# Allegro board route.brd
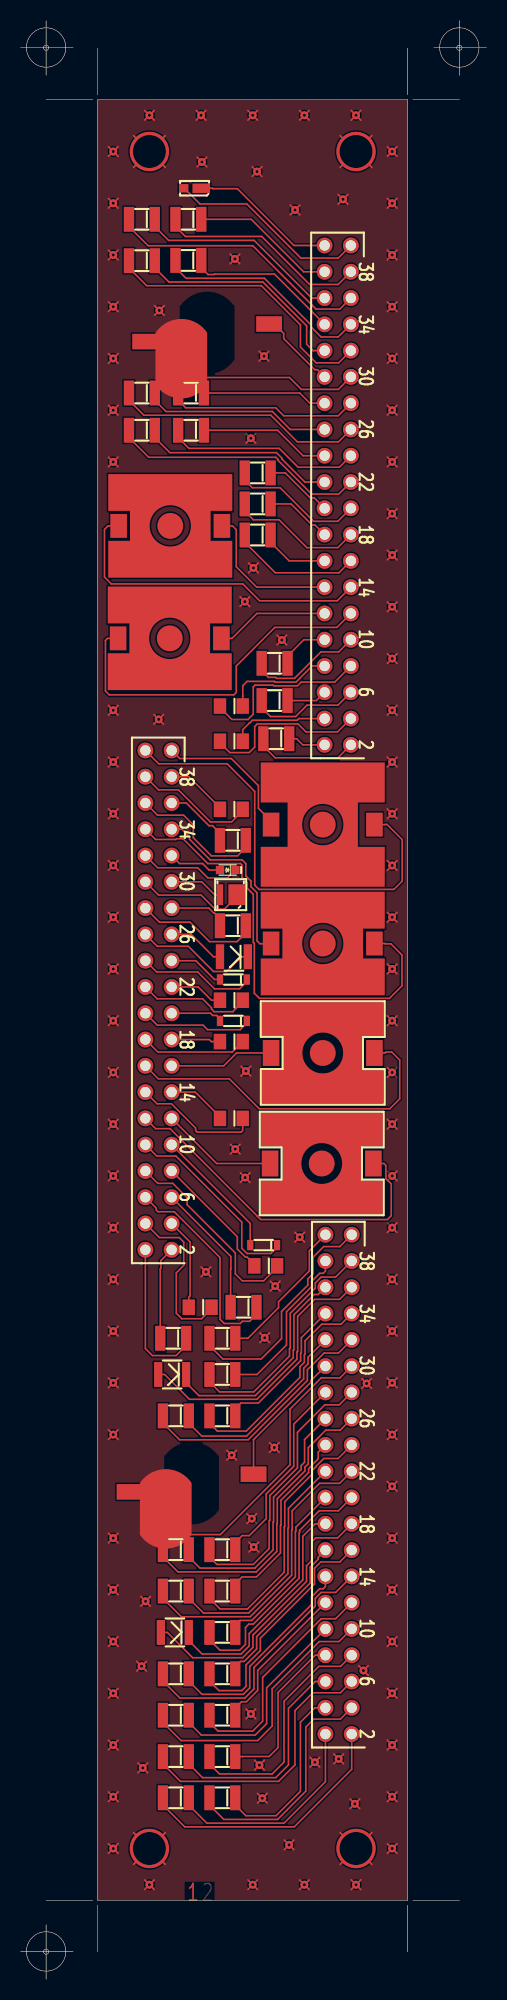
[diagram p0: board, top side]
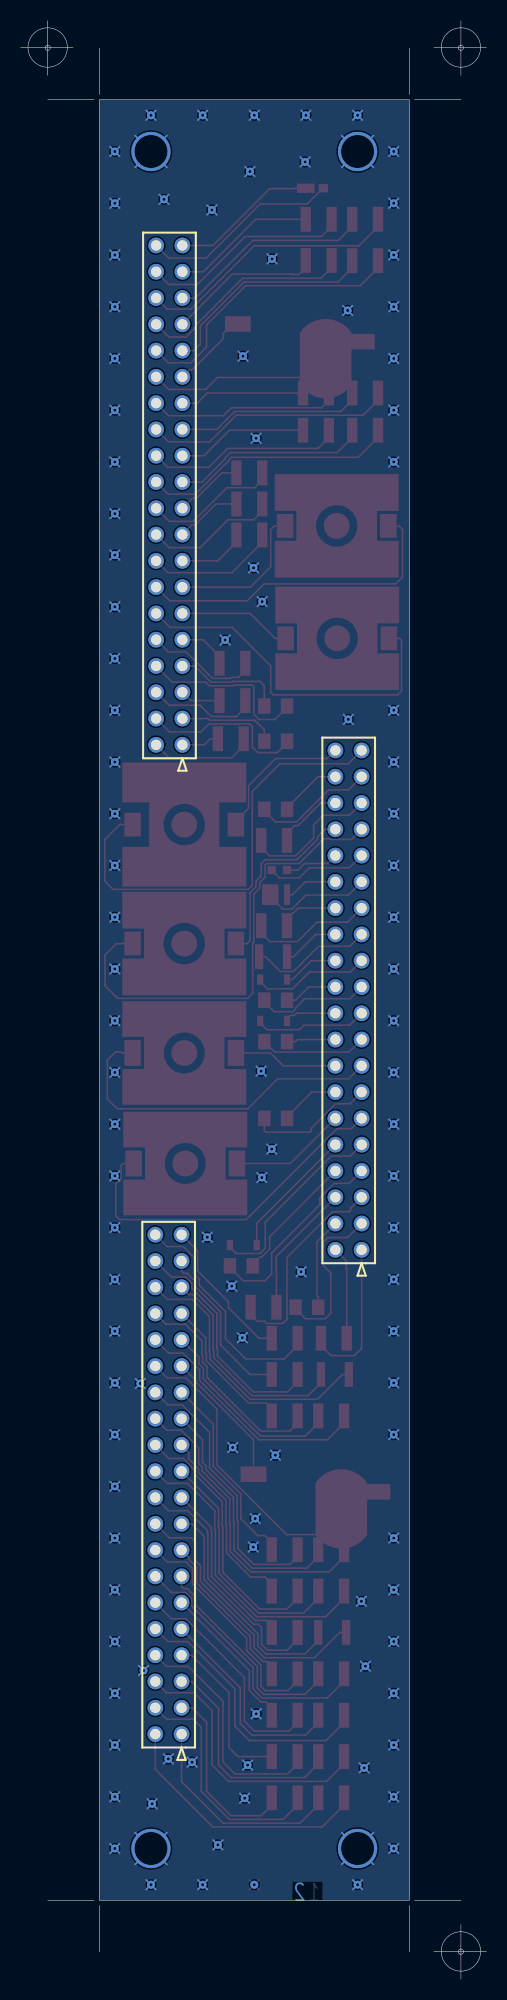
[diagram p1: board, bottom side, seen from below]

Outline 45.08 x 189.28 mm; copper layers: TOP, BOTTOM. Coordinates in mm from the lower left corner of the outline.
Outline path: circle c2.46,186.69 r1.9 ; circle c2.46,186.67 r0.25 ; circle c42.46,186.69 r1.91 ; circle c42.46,186.67 r0.25 ; 0,186.67 5.08,186.67 ; 2.46,189.28 2.46,184 ; 6.96,181.64 2.46,181.64 ; 6.96,7.64 2.46,7.64 ; 7.46,182.14 7.46,186.64 ; 7.46,7.14 7.46,2.64 ; 37.46,182.14 37.46,186.64 ; 37.46,7.14 37.46,2.64 ; 37.96,181.64 42.46,181.64 ; 37.96,7.64 42.46,7.64 ; 40,186.67 45.08,186.67 ; 42.46,189.28 42.46,184 ; 7.46,181.64 37.46,181.64 37.46,7.64 7.46,7.64 7.46,181.64

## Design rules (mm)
constraint set DEFAULT: min track width 0.15, pair gap 0.15

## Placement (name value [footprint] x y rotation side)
D1  -  [LED_JCLMS]  15.88 173.09 270 top
D2  -  [LED_SMC]  14.98 170.09 0 top
D3  -  [LED_SMC]  10.48 170.09 0 top
D4  -  [LED_SMC]  14.98 166.11 0 top
D5  -  [LED_SMC]  10.48 166.09 0 top
D6  -  [LED_APG2C1]  12.05 158.27 270 top
D7  -  [LED_SMC]  15.24 153.3 0 top
D8  -  [LED_SMC]  10.48 153.3 0 top
D9  -  [LED_SMC]  15.24 149.7 0 top
D10  -  [LED_SMC]  10.48 149.7 0 top
D11  -  [LED_SMC]  21.69 145.58 0 top
D12  -  [LED_SMC]  21.69 142.58 0 top
D13  -  [LED_SMC]  21.69 139.58 0 top
D14  -  [LED_LB_W5SM]  9.48 140.46 0 top
D15  -  [LED_LB_W5SM]  9.43 129.59 0 top
D16  -  [LED_SMC]  23.33 127.18 0 top
D17  -  [SLED23X15_0805]  19.29 123.05 0 top
D18  -  [LED_SMC]  23.33 123.58 0 top
D19  -  [SLED23X15_0805]  19.29 119.65 0 top
D20  -  [LED_SMC]  23.49 119.89 0 top
D21  -  [LED_LV_W5AM]  24.24 111.59 0 top
D22  -  [SLED23X15_0805]  19.29 113.07 0 top
D23  -  [LED_SMC]  19.29 110.07 0 top
D24  -  [LED_LB_W5SM]  24.24 100.1 0 top
D25  -  [SLED16X8_0603]  19.29 107.2 0 top
D26  -  [SLED_PSLM31]  19.29 104.82 0 top
D27  -  [LED_SMC]  19.29 101.82 0 top
D28  -  [LED_SMT]  19.29 98.82 0 top
D29  -  [SLED32X10_1204]  19.29 96.62 90 top
D30  -  [SLED23X15_0805]  19.29 94.62 0 top
D31  -  [SLED32X10_1204]  19.29 92.62 90 top
D32  -  [SLED23X15_0805]  19.29 90.62 0 top
D33  -  [LED_LR_W5SM]  24.24 89.52 0 top
D34  -  [SLED23X15_0805]  19.29 83.2 0 top
D35  -  [LED_LR_W5SM]  24.14 78.84 0 top
D36  -  [SLED32X10_1204]  22.22 70.95 90 top
D37  -  [SLED23X15_0805]  22.62 68.95 0 top
D38  -  [LED_SMC]  20.32 64.95 0 top
D39  -  [SLED23X15_0805]  16.27 64.95 0 top
D40  -  [LED_SMC]  13.51 61.95 0 top
D41  -  [LED_SMC]  18.27 61.95 0 top
D42  -  [LED_SMC]  18.27 58.45 0 top
D43  -  [LED_SMT]  13.31 58.45 0 top
D44  -  [LED_SMC]  18.27 54.45 0 top
D45  -  [LED_SMC]  13.77 54.45 0 top
D46  -  [LED_APG2C1]  10.54 47.11 270 top
D47  -  [LED_SMC]  18.27 41.52 0 top
D48  -  [LED_SMC]  13.77 41.52 0 top
D49  -  [LED_SMC]  18.27 37.52 0 top
D50  -  [LED_SMC]  13.77 37.52 0 top
D51  -  [LED_SMC]  18.27 33.52 0 top
D52  -  [LED_SMT]  13.57 33.52 0 top
D53  -  [LED_SMC]  18.27 29.52 0 top
D54  -  [LED_SMC]  13.77 29.52 0 top
D55  -  [LED_SMC]  18.27 25.52 0 top
D56  -  [LED_SMC]  13.77 25.52 0 top
D57  -  [LED_SMC]  18.27 21.52 0 top
D58  -  [LED_SMC]  13.77 21.52 0 top
D59  -  [LED_SMC]  18.27 17.54 0 top
D60  -  [LED_SMC]  13.77 17.54 0 top
J1  -  [CONHE13D2X20M]  29.42 119.3 180 bottom
J2  -  [CONHE13D2X20M]  12.07 70.5 180 bottom
J3  -  [CONHE13D2X20M]  29.5 23.7 180 bottom
NOREF  -  []  2.46 2.64 0 top
NOREF#2  -  []  7.46 7.64 90 top
NOREF#3  -  []  7.46 7.64 0 top

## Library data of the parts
D1 = LED: part number: GW-JCLMS1
D2 = LED: part number: RLCU-355
D3 = LED: part number: RLCU-365
D4 = LED: part number: UVLED365_SMD
D5 = LED: part number: RLCU-375
D6 = LED: part number: APG2C1_375
D7 = LED: part number: RLCU-380
D8 = LED: part number: SMC395
D9 = LED: part number: RLCU-400
D10 = LED: part number: SMC405
D11 = LED: part number: RLCU-410
D12 = LED: part number: SMC415
D13 = LED: part number: SMC430
D14 = LED: part number: LD_W5AM_1U4U_35
D15 = LED: part number: LB_W5SM_FZH_35
D16 = LED: part number: SMC470
D17 = LED: part number: 598-8191-107F
D18 = LED: part number: SMC490
D19 D22 = LED: part number: 598-8181-107F
D20 = LED: part number: RLCU
D21 = LED: part number: LV_W5AM_JZKZ_25
D23 = LED: part number: SMC525
D24 = LED: part number: LT_W5SM-JYKI-25
D25 = LED: part number: LTQ39G
D26 = LED: part number: PSLM31.13
D27 = LED: part number: SMC565
D28 = LED: part number: SMT570
D29 = LED: part number: SM1204SGC
D30 = LED: part number: 598-8150-107F
D31 = LED: part number: SM1204UYC
D32 = LED: part number: 598-8140-107F
D33 = LED: part number: LY_W5SM_HZJZ_46
D34 = LED: part number: 598-8130-107F
D35 = LED: part number: LA_W5SM_JYKY_24
D36 = LED: part number: SM1204UOC
D37 = LED: part number: 598-8120-107F
D38 = LED: part number: SMC630
D39 = LED: part number: 598-8110-107F
D40 D59 D60 = LED: part number: SMCXXX
D41 = LED: part number: SMC660N
D42 = LED: part number: SMC680
D43 = LED: part number: SMT700
D44 = LED: part number: SMC720
D45 = LED: part number: SMC735
D46 = LED: part number: APG2C1_740
D47 = LED: part number: SMC750
D48 = LED: part number: SMC770
D49 = LED: part number: SMC780
D50 = LED: part number: SMC810
D51 = LED: part number: SMC830
D52 = LED: part number: SMT850N
D53 = LED: part number: SMC870
D54 = LED: part number: SMC890
D55 = LED: part number: SMC910
D56 = LED: part number: SMC940
D57 = LED: part number: SMC970
D58 = LED: part number: SMC1050
J1-J3 = CON40P: part number: CON40P-HE13D

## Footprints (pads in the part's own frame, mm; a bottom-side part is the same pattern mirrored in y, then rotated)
CONHE13D2X20M
  round 1.52 hole 1: 1(0,0) 2(-2.54,0) 3(0,2.54) 4(-2.54,2.54) 5(0,5.08) 6(-2.54,5.08) 7(0,7.62) 8(-2.54,7.62) 9(0,10.16) 10(-2.54,10.16) 11(0,12.7) 12(-2.54,12.7) 13(0,15.24) 14(-2.54,15.24) 15(0,17.78) 16(-2.54,17.78) 17(0,20.32) 18(-2.54,20.32) 19(0,22.86) 20(-2.54,22.86) 21(0,25.4) 22(-2.54,25.4) 23(0,27.94) 24(-2.54,27.94) 25(0,30.48) 26(-2.54,30.48) 27(0,33.02) 28(-2.54,33.02) 29(0,35.56) 30(-2.54,35.56) 31(0,38.1) 32(-2.54,38.1) 33(0,40.64) 34(-2.54,40.64) 35(0,43.18) 36(-2.54,43.18) 37(0,45.72) 38(-2.54,45.72) 39(0,48.26) 40(-2.54,48.26)
LED_APG2C1
  custom 1.25x1.25 smd: (1.65,3.5)
  rect 1.5x2.5 smd: 1(0,0) 2(-1.7,12)
LED_JCLMS
  rect 0.8x0.9 smd: 1(0,-0.1)
  rect 0.9x1.7 smd: 2(0,1.6)
LED_LB_W5SM
  round 2.5 smd: (5,0)
  rect 1.6x2.3 smd: 1(0,0) 2(10,0)
LED_LR_W5SM
  round 2.5 smd: (5,0)
  rect 1.6x2.5 smd: 1(0,0) 2(10,0)
LED_LV_W5AM
  round 2.5 smd: (5,0)
  rect 1.6x2.3 smd: 1(0,0) 2(10,0)
LED_SMC
  rect 1x2.4 smd: 1(0,0) 2(2.5,0)
LED_SMT
  rect 0.8x2.4 smd: 1(0,0) 2(2.7,0)
SLED16X8_0603
  rect 0.8x0.8 smd: 1(0,0) 2(1.5,0)
SLED23X15_0805
  rect 1.2x1.5 smd: 1(0,0) 2(2.2,0)
SLED32X10_1204
  rect 1x0.6 smd: 1(0,0) 2(0,-2.6)
SLED_PSLM31
  rect 0.6x2 smd: 1(0,0)
  rect 1.6x2 smd: 2(1.62,0)

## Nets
UNNAMED_1_CON40P_I2_A: D4.2(K) J1.33
UNNAMED_1_CON40P_I2_A_1: D20.2(K) J1.1
UNNAMED_1_CON40P_I2_A_2: D18.1 J1.6
UNNAMED_1_CON40P_I2_A_3: D5.1 J1.32
UNNAMED_1_CON40P_I2_A_4: D5.2(K) J1.31
UNNAMED_1_CON40P_I2_A_5: D6.1 J1.30
UNNAMED_1_CON40P_I2_A_6: D6.2(K) J1.29
UNNAMED_1_CON40P_I2_A_7: D4.1 J1.34
UNNAMED_1_CON40P_I2_A_8: D10.1 J1.22
UNNAMED_1_CON40P_I2_A_9: D10.2(K) J1.21
UNNAMED_1_CON40P_I2_A_10: D8.1 J1.26
UNNAMED_1_CON40P_I2_A_11: D15.2(K) J1.11
UNNAMED_1_CON40P_I2_A_12: D15.1 J1.12
UNNAMED_1_CON40P_I2_A_13: D8.2(K) J1.25
UNNAMED_1_CON40P_I2_A_14: D7.1 J1.28
UNNAMED_1_CON40P_I2_A_15: D7.2(K) J1.27
UNNAMED_1_CON40P_I2_A_16: D14.1 J1.14
UNNAMED_1_CON40P_I2_A_17: D14.2(K) J1.13
UNNAMED_1_CON40P_I2_A_18: D13.1 J1.16
UNNAMED_1_CON40P_I2_A_19: D13.2(K) J1.15
UNNAMED_1_CON40P_I2_A_20: D12.1 J1.18
UNNAMED_1_CON40P_I2_A_21: D12.2(K) J1.17
UNNAMED_1_CON40P_I2_A_22: D9.2(K) J1.23
UNNAMED_1_CON40P_I2_A_23: D9.1 J1.24
UNNAMED_1_CON40P_I2_A_24: D11.2(K) J1.19
UNNAMED_1_CON40P_I2_A_25: D11.1 J1.20
UNNAMED_1_CON40P_I2_A_26: D16.2(K) J1.9
UNNAMED_1_CON40P_I2_A_27: D16.1 J1.10(A<9>)
UNNAMED_1_CON40P_I2_A_28: D17.1 J1.8
UNNAMED_1_CON40P_I2_A_29: D17.2(K) J1.7
UNNAMED_1_CON40P_I2_A_30: D18.2(K) J1.5
UNNAMED_1_CON40P_I2_A_31: D20.1 J1.2
UNNAMED_1_CON40P_I2_A_32: D19.2(K) J1.3
UNNAMED_1_CON40P_I2_A_33: D19.1 J1.4
UNNAMED_1_CON40P_I2_A_34: D3.1 J1.36
UNNAMED_1_CON40P_I2_A_35: D2.1 J1.38
UNNAMED_1_CON40P_I2_A_36: D2.2(K) J1.37
UNNAMED_1_CON40P_I2_A_37: D3.2(K) J1.35
UNNAMED_1_CON40P_I2_A_38: D1.2(K) J1.39
UNNAMED_1_CON40P_I2_A_39: D1.1 J1.40
UNNAMED_1_CON40P_I21_A: D35.2(K) J2.11
UNNAMED_1_CON40P_I21_A_1: D23.2(K) J2.35
UNNAMED_1_CON40P_I21_A_2: D23.1 J2.36
UNNAMED_1_CON40P_I21_A_3: D35.1 J2.12
UNNAMED_1_CON40P_I21_A_4: D27.2(K) J2.27
UNNAMED_1_CON40P_I21_A_5: D27.1 J2.28
UNNAMED_1_CON40P_I21_A_6: D33.2(K) J2.15
UNNAMED_1_CON40P_I21_A_7: D33.1 J2.16
UNNAMED_1_CON40P_I21_A_8: D24.2(K) J2.33
UNNAMED_1_CON40P_I21_A_9: D24.1 J2.34
UNNAMED_1_CON40P_I21_A_10: D30.1 J2.22
UNNAMED_1_CON40P_I21_A_11: D21.2(K) J2.39
UNNAMED_1_CON40P_I21_A_12: D30.2(K) J2.21
UNNAMED_1_CON40P_I21_A_13: D21.1 J2.40
UNNAMED_1_CON40P_I21_A_14: D32.1 J2.18
UNNAMED_1_CON40P_I21_A_15: D32.2(K) J2.17
UNNAMED_1_CON40P_I21_A_16: D40.2(K) J2.1
UNNAMED_1_CON40P_I21_A_17: D40.1 J2.2
UNNAMED_1_CON40P_I21_A_18: D22.2(K) J2.37
UNNAMED_1_CON40P_I21_A_19: D22.1 J2.38
UNNAMED_1_CON40P_I21_A_20: D39.2(K) J2.3
UNNAMED_1_CON40P_I21_A_21: D37.1 J2.8
UNNAMED_1_CON40P_I21_A_22: D39.1 J2.4
UNNAMED_1_CON40P_I21_A_23: D37.2(K) J2.7
UNNAMED_1_CON40P_I21_A_24: D25.2(K) J2.31
UNNAMED_1_CON40P_I21_A_25: D25.1 J2.32
UNNAMED_1_CON40P_I21_A_26: D38.1 J2.6
UNNAMED_1_CON40P_I21_A_27: D28.2(K) J2.25
UNNAMED_1_CON40P_I21_A_28: D38.2(K) J2.5
UNNAMED_1_CON40P_I21_A_29: D28.1 J2.26
UNNAMED_1_CON40P_I21_A_30: D36.1 J2.10(A<9>)
UNNAMED_1_CON40P_I21_A_31: D31.1 J2.20
UNNAMED_1_CON40P_I21_A_32: D34.1 J2.14
UNNAMED_1_CON40P_I21_A_33: D34.2(K) J2.13
UNNAMED_1_CON40P_I21_A_34: D29.1 J2.24
UNNAMED_1_CON40P_I21_A_35: D36.2(K) J2.9
UNNAMED_1_CON40P_I21_A_36: D31.2(K) J2.19
UNNAMED_1_CON40P_I21_A_37: D29.2(K) J2.23
UNNAMED_1_CON40P_I21_A_38: D26.1 J2.30
UNNAMED_1_CON40P_I21_A_39: D26.2(K) J2.29
UNNAMED_1_CON40P_I55_A: D46.2(K) J3.29
UNNAMED_1_CON40P_I55_A_1: D46.1 J3.30
UNNAMED_1_CON40P_I55_A_2: D41.1 J3.40
UNNAMED_1_CON40P_I55_A_3: D41.2(K) J3.39
UNNAMED_1_CON40P_I55_A_4: D58.1 J3.6
UNNAMED_1_CON40P_I55_A_5: D58.2(K) J3.5
UNNAMED_1_CON40P_I55_A_6: D55.1 J3.12
UNNAMED_1_CON40P_I55_A_7: D55.2(K) J3.11
UNNAMED_1_CON40P_I55_A_8: D56.1 J3.10(A<9>)
UNNAMED_1_CON40P_I55_A_9: D57.1 J3.8
UNNAMED_1_CON40P_I55_A_10: D56.2(K) J3.9
UNNAMED_1_CON40P_I55_A_11: D57.2(K) J3.7
UNNAMED_1_CON40P_I55_A_12: D54.1 J3.14
UNNAMED_1_CON40P_I55_A_13: D54.2(K) J3.13
UNNAMED_1_CON40P_I55_A_14: D53.1 J3.16
UNNAMED_1_CON40P_I55_A_15: D53.2(K) J3.15
UNNAMED_1_CON40P_I55_A_16: D59.2(K) J3.3
UNNAMED_1_CON40P_I55_A_17: D59.1 J3.4
UNNAMED_1_CON40P_I55_A_18: D51.1 J3.20
UNNAMED_1_CON40P_I55_A_19: D51.2(K) J3.19
UNNAMED_1_CON40P_I55_A_20: D48.1 J3.26
UNNAMED_1_CON40P_I55_A_21: D48.2(K) J3.25
UNNAMED_1_CON40P_I55_A_22: D49.1 J3.24
UNNAMED_1_CON40P_I55_A_23: D49.2(K) J3.23
UNNAMED_1_CON40P_I55_A_24: D50.1 J3.22
UNNAMED_1_CON40P_I55_A_25: D50.2(K) J3.21
UNNAMED_1_CON40P_I55_A_26: D47.1 J3.28
UNNAMED_1_CON40P_I55_A_27: D47.2(K) J3.27
UNNAMED_1_CON40P_I55_A_28: D60.2(K) J3.1
UNNAMED_1_CON40P_I55_A_29: D60.1 J3.2
UNNAMED_1_CON40P_I55_A_30: D45.1 J3.32
UNNAMED_1_CON40P_I55_A_31: D45.2(K) J3.31
UNNAMED_1_CON40P_I55_A_32: D43.2(K) J3.35
UNNAMED_1_CON40P_I55_A_33: D43.1 J3.36
UNNAMED_1_CON40P_I55_A_34: D44.1 J3.34
UNNAMED_1_CON40P_I55_A_35: D44.2(K) J3.33
UNNAMED_1_CON40P_I55_A_36: D52.2(K) J3.17
UNNAMED_1_CON40P_I55_A_37: D42.1 J3.38
UNNAMED_1_CON40P_I55_A_38: D42.2(K) J3.37
UNNAMED_1_CON40P_I55_A_39: D52.1 J3.18

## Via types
v1: diameter 0.77, hole 0.3, TOP to BOTTOM, 107 vias
v2: diameter 3.8, hole 3.2, TOP to BOTTOM, 4 vias

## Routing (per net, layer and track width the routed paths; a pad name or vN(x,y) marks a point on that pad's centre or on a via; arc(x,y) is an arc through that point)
GND: length 623.5
  TOP w0.15: v1(27.46,180.14) 27.93,179.68 ; v1(27.46,180.14) 27,179.68 ; v1(27.46,180.14) 27.93,180.61 ; v1(27.46,180.14) 27,180.61 ; v1(13.36,121.76) 13.83,122.23 ; v1(13.36,121.76) 12.9,122.23 ; v1(13.36,121.76) 12.9,121.3 ; v1(13.36,121.76) 13.83,121.3 ; v1(23.55,156.86) 24.02,156.4 ; v1(23.55,156.86) 23.09,156.4 ; v1(23.55,156.86) 23.09,157.33 ; v1(23.55,156.86) 24.02,157.33 ; v1(22.37,44.52) 22.84,44.99 ; v1(22.37,44.52) 21.91,44.99 ; v1(22.37,44.52) 21.91,44.06 ; v1(35.96,82.64) 36.43,82.18 ; v1(35.96,82.64) 36.43,83.11 ; v1(35.96,82.64) 35.5,82.18 ; v1(35.96,82.64) 35.5,83.11 ; 35.5,23.11 v1(35.96,22.64) ; v1(35.96,22.64) 35.5,22.18 ; v1(35.96,22.64) 36.43,23.11 ; v1(35.96,22.64) 36.43,22.18 ; 8.5,33.11 v1(8.96,32.64) ; v1(8.96,32.64) 9.43,32.18 ; v1(8.96,32.64) 9.43,33.11 ; v1(8.96,32.64) 8.5,32.18 ; 35.5,47.18 v1(35.96,47.64) ; v1(35.96,47.64) 36.43,48.11 ; v1(35.96,47.64) 36.43,47.18 ; v1(35.96,47.64) 35.5,48.11 ; v1(21.8,87.77) 22.27,88.24 ; v1(21.8,87.77) 21.34,88.24 ; v1(21.8,87.77) 21.34,87.31 ; v1(21.8,87.77) 22.27,87.31 ; 22.93,17.04 v1(23.39,17.5) ; v1(23.39,17.5) 22.93,17.97 ; v1(23.39,17.5) 23.86,17.04 ; v1(23.39,17.5) 23.86,17.97 ; v1(21.73,77.48) 22.2,77.95 ; v1(21.73,77.48) 22.2,77.02 ; v1(21.73,77.48) 21.27,77.02 ; v1(21.73,77.48) 21.27,77.95 ; 20.31,80.7 v1(20.77,80.23) ; v1(20.77,80.23) 20.31,79.77 ; v1(20.77,80.23) 21.24,79.77 ; v1(20.77,80.23) 21.24,80.7 ; v1(22.46,9.14) 22.93,8.68 ; v1(22.46,9.14) 22.93,9.61 ; v1(22.46,9.14) 22,8.68 ; v1(22.46,9.14) 22,9.61 ; 8.5,27.18 v1(8.96,27.64) ; v1(8.96,27.64) 8.5,28.11 ; v1(8.96,27.64) 9.43,27.18 ; v1(8.96,27.64) 9.43,28.11 ; 35.5,88.11 v1(35.96,87.64) 35.5,87.18 ; 35.5,108.11 v1(35.96,107.64) ; v1(35.96,107.64) 35.5,107.18 ; v1(35.96,107.64) 36.43,107.18 ; v1(35.96,107.64) 36.43,108.11 ; v1(32.35,16.96) 32.82,16.5 ; v1(32.35,16.96) 32.82,17.43 ; v1(32.35,16.96) 31.89,17.43 ; v1(32.35,16.96) 31.89,16.5 ; v1(8.96,22.64) 9.43,22.18 ; v1(8.96,22.64) 8.5,23.11 ; v1(8.96,22.64) 9.43,23.11 ; v1(8.96,22.64) 8.5,22.18 ; 33.03,57.12 v1(33.49,57.58) ; v1(33.49,57.58) 33.96,58.05 ; v1(33.49,57.58) 33.03,58.05 ; v1(33.49,57.58) 33.96,57.12 ; 8.5,122.18 v1(8.96,122.64) ; v1(8.96,122.64) 9.43,123.11 ; v1(8.96,122.64) 9.43,122.18 ; v1(8.96,122.64) 8.5,123.11 ; 8.5,13.11 v1(8.96,12.64) ; v1(8.96,12.64) 9.43,12.18 ; v1(8.96,12.64) 9.43,13.11 ; v1(8.96,12.64) 8.5,12.18 ; v1(8.96,67.64) 9.43,67.18 ; v1(8.96,67.64) 8.5,67.18 ; v1(8.96,67.64) 9.43,68.11 ; v1(8.96,67.64) 8.5,68.11 ; v1(8.96,156.64) 9.43,156.18 ; v1(8.96,156.64) 8.5,156.18 ; v1(8.96,156.64) 8.5,157.11 ; v1(8.96,156.64) 9.43,157.11 ; v1(17.54,175.63) 18.01,175.17 ; v1(17.54,175.63) 18.01,176.1 ; v1(17.54,175.63) 17.08,175.17 ; v1(17.54,175.63) 17.08,176.1 ; 8.5,73.11 v1(8.96,72.64) ; v1(8.96,72.64) 8.5,72.18 ; v1(8.96,72.64) 9.43,72.18 ; v1(8.96,72.64) 9.43,73.11 ; 22,179.68 v1(22.46,180.14) ; v1(22.46,180.14) 22,180.61 ; v1(22.46,180.14) 22.93,179.68 ; v1(22.46,180.14) 22.93,180.61 ; v1(21.7,133.14) 22.17,133.61 ; v1(21.7,133.14) 22.17,132.68 ; v1(21.7,133.14) 21.24,132.68 ; v1(21.7,133.14) 21.24,133.61 ; v1(23.11,20.7) 23.58,21.17 ; v1(23.11,20.7) 22.65,21.17 ; v1(23.11,20.7) 22.65,20.24 ; v1(23.11,20.7) 23.58,20.24 ; v2(32.46,176.64) 34,175.11 ; v2(32.46,176.64) 30.93,178.18 ; v2(32.46,176.64) 30.93,175.11 ; v2(32.46,176.64) 34,178.18 ; 35.5,142.11 v1(35.96,141.64) ; v1(35.96,141.64) 36.43,142.11 ; v1(35.96,141.64) 35.5,141.18 ; v1(35.96,141.64) 36.43,141.18 ; 8.5,88.11 v1(8.96,87.64) ; v1(8.96,87.64) 9.43,88.11 ; v1(8.96,87.64) 9.43,87.18 ; v1(8.96,87.64) 8.5,87.18 ; v1(32.46,9.14) 32.93,8.68 ; v1(32.46,9.14) 32,9.61 ; v1(32.46,9.14) 32,8.68 ; v1(32.46,9.14) 32.93,9.61 ; 8.5,147.11 v1(8.96,146.64) ; v1(8.96,146.64) 8.5,146.18 ; v1(8.96,146.64) 9.43,147.11 ; v1(8.96,146.64) 9.43,146.18 ; v1(35.96,137.64) 36.43,138.11 ; v1(35.96,137.64) 35.5,137.18 ; v1(35.96,137.64) 36.43,137.18 ; v1(35.96,137.64) 35.5,138.11 ; 8.5,58.11 v1(8.96,57.64) ; v1(8.96,57.64) 9.43,58.11 ; v1(8.96,57.64) 8.5,57.18 ; v1(8.96,57.64) 9.43,57.18 ; 35.5,167.11 v1(35.96,166.64) ; v1(35.96,166.64) 36.43,167.11 ; v1(35.96,166.64) 36.43,166.18 ; v1(35.96,166.64) 35.5,166.18 ; 8.5,112.18 v1(8.96,112.64) ; v1(8.96,112.64) 9.43,112.18 ; v1(8.96,112.64) 8.5,113.11 ; v1(8.96,112.64) 9.43,113.11 ; v1(35.96,92.64) 36.43,92.18 ; v1(35.96,92.64) 36.43,93.11 ; v1(35.96,92.64) 35.5,92.18 ; v1(35.96,92.64) 35.5,93.11 ; 11.24,30.73 v1(11.7,30.26) ; v1(11.7,30.26) 12.17,30.73 ; v1(11.7,30.26) 12.17,29.8 ; v1(11.7,30.26) 11.24,29.8 ; 8.5,92.18 v1(8.96,92.64) ; v1(8.96,92.64) 9.43,93.11 ; v1(8.96,92.64) 9.43,92.18 ; v1(8.96,92.64) 8.5,93.11 ; v1(35.96,42.64) 36.43,43.11 ; v1(35.96,42.64) 36.43,42.18 ; v1(35.96,42.64) 35.5,42.18 ; v1(35.96,42.64) 35.5,43.11 ; v1(35.96,122.64) 36.43,123.11 ; v1(35.96,122.64) 35.5,122.18 ; v1(35.96,122.64) 36.43,122.18 ; v1(35.96,122.64) 35.5,123.11 ; 21.82,148.47 v1(22.28,148.93) 22.75,148.47 ; 8.5,177.11 v1(8.96,176.64) ; v1(8.96,176.64) 9.43,177.11 ; v1(8.96,176.64) 9.43,176.18 ; v1(8.96,176.64) 8.5,176.18 ; 35.5,177.11 v1(35.96,176.64) ; v1(35.96,176.64) 36.43,177.11 ; v1(35.96,176.64) 35.5,176.18 ; v1(35.96,176.64) 36.43,176.18 ; 30.93,11.11 v2(32.46,12.64) ; v2(32.46,12.64) 34,14.18 ; v2(32.46,12.64) 30.93,14.18 ; v2(32.46,12.64) 34,11.11 ; 8.5,98.11 v1(8.96,97.64) ; v1(8.96,97.64) 8.5,97.18 ; v1(8.96,97.64) 9.43,97.18 ; v1(8.96,97.64) 9.43,98.11 ; v1(8.96,17.64) 9.43,18.11 ; v1(8.96,17.64) 8.5,18.11 ; v1(8.96,17.64) 9.43,17.18 ; v1(8.96,17.64) 8.5,17.18 ; v1(22.88,174.7) 23.35,174.24 ; v1(22.88,174.7) 23.35,175.17 ; v1(22.88,174.7) 22.42,174.24 ; v1(22.88,174.7) 22.42,175.17 ; 8.5,63.11 v1(8.96,62.64) ; v1(8.96,62.64) 9.43,63.11 ; v1(8.96,62.64) 9.43,62.18 ; v1(8.96,62.64) 8.5,62.18 ; v1(35.96,97.64) 36.43,97.18 ; v1(35.96,97.64) 35.5,98.11 ; v1(35.96,97.64) 35.5,97.18 ; v1(35.96,97.64) 36.43,98.11 ; 35.5,146.18 v1(35.96,146.64) ; v1(35.96,146.64) 36.43,147.11 ; v1(35.96,146.64) 35.5,147.11 ; v1(35.96,146.64) 36.43,146.18 ; 35.5,58.11 v1(35.96,57.64) ; v1(35.96,57.64) 36.43,58.11 ; v1(35.96,57.64) 35.5,57.18 ; v1(35.96,57.64) 36.43,57.18 ; v1(35.96,17.64) 36.43,17.18 ; v1(35.96,17.64) 35.5,18.11 ; v1(35.96,17.64) 36.43,18.11 ; v1(35.96,17.64) 35.5,17.18 ; 24.09,51.86 v1(24.55,51.39) ; v1(24.55,51.39) 25.02,51.86 ; v1(24.55,51.39) 24.09,50.93 ; v1(24.55,51.39) 25.02,50.93 ; v1(17.46,180.14) 17.93,179.68 ; v1(17.46,180.14) 17,179.68 ; v1(17.46,180.14) 17,180.61 ; v1(17.46,180.14) 17.93,180.61 ; 35.5,172.11 v1(35.96,171.64) ; v1(35.96,171.64) 36.43,171.18 ; v1(35.96,171.64) 35.5,171.18 ; v1(35.96,171.64) 36.43,172.11 ; v1(8.96,107.64) 9.43,107.18 ; v1(8.96,107.64) 8.5,108.11 ; v1(8.96,107.64) 8.5,107.18 ; v1(8.96,107.64) 9.43,108.11 ; v1(35.96,72.64) 36.43,72.18 ; v1(35.96,72.64) 36.43,73.11 ; v1(35.96,72.64) 35.5,72.18 ; v1(27.46,9.14) 27.93,9.61 ; v1(27.46,9.14) 27.93,8.68 ; v1(27.46,9.14) 27,9.61 ; v1(27.46,9.14) 27,8.68 ; 23.16,62.47 v1(23.62,62) ; v1(23.62,62) 24.09,62.47 ; v1(23.62,62) 23.16,61.54 ; v1(23.62,62) 24.09,61.54 ; 20.28,166.73 v1(20.74,166.26) ; v1(20.74,166.26) 21.21,166.73 ; v1(20.74,166.26) 21.21,165.8 ; v1(20.74,166.26) 20.28,165.8 ; 8.5,172.11 v1(8.96,171.64) ; v1(8.96,171.64) 9.43,172.11 ; v1(8.96,171.64) 9.43,171.18 ; v1(8.96,171.64) 8.5,171.18 ; v1(27.01,71.72) 27.48,72.19 ; v1(27.01,71.72) 26.55,72.19 ; v1(27.01,71.72) 27.48,71.26 ; v1(27.01,71.72) 26.55,71.26 ; 22.1,42.24 v1(22.56,41.77) ; v1(22.56,41.77) 22.1,41.31 ; v1(22.56,41.77) 23.03,42.24 ; v1(22.56,41.77) 23.03,41.31 ; 11.63,36.07 v1(12.09,36.53) ; v1(12.09,36.53) 12.56,37 ; v1(12.09,36.53) 11.63,37 ; v1(12.09,36.53) 12.56,36.07 ; v1(8.96,52.64) 9.43,53.11 ; v1(8.96,52.64) 8.5,53.11 ; v1(8.96,52.64) 8.5,52.18 ; v1(8.96,52.64) 9.43,52.18 ; v1(8.96,117.64) 9.43,118.11 ; v1(8.96,117.64) 8.5,117.18 ; v1(8.96,117.64) 9.43,117.18 ; v1(8.96,117.64) 8.5,118.11 ; v1(17.93,68.37) 18.4,68.84 ; v1(17.93,68.37) 17.47,68.84 ; v1(17.93,68.37) 17.47,67.91 ; v1(17.93,68.37) 18.4,67.91 ; v1(28.48,20.98) 28.95,21.45 ; v1(28.48,20.98) 28.02,21.45 ; v1(28.48,20.98) 28.02,20.52 ; v1(28.48,20.98) 28.95,20.52 ; 22.07,136.87 v1(22.53,136.4) ; v1(22.53,136.4) 23,135.94 ; v1(22.53,136.4) 23,136.87 ; v1(22.53,136.4) 22.07,135.94 ; 30.32,20.84 v1(30.78,21.3) ; v1(30.78,21.3) 30.32,21.77 ; v1(30.78,21.3) 31.25,21.77 ; v1(30.78,21.3) 31.25,20.84 ; 26.1,171.46 v1(26.56,170.99) ; v1(26.56,170.99) 26.1,170.53 ; v1(26.56,170.99) 27.03,171.46 ; v1(26.56,170.99) 27.03,170.53 ; v1(35.96,52.64) 36.43,53.11 ; v1(35.96,52.64) 35.5,52.18 ; v1(35.96,52.64) 36.43,52.18 ; v1(35.96,52.64) 35.5,53.11 ; v1(12.46,9.14) 12.93,8.68 ; v1(12.46,9.14) 12,9.61 ; v1(12.46,9.14) 12,8.68 ; v1(12.46,9.14) 12.93,9.61 ; 8.5,42.18 v1(8.96,42.64) ; v1(8.96,42.64) 9.43,42.18 ; v1(8.96,42.64) 8.5,43.11 ; v1(8.96,42.64) 9.43,43.11 ; v1(35.96,117.64) 36.43,118.11 ; v1(35.96,117.64) 35.5,117.18 ; v1(35.96,117.64) 36.43,117.18 ; v1(35.96,117.64) 35.5,118.11 ; 35.5,102.18 v1(35.96,102.64) ; v1(35.96,102.64) 36.43,102.18 ; v1(35.96,102.64) 36.43,103.11 ; v1(35.96,102.64) 35.5,103.11 ; 19.96,50.19 v1(20.42,50.65) ; v1(20.42,50.65) 20.89,50.19 ; v1(20.42,50.65) 20.89,51.12 ; v1(20.42,50.65) 19.96,51.12 ; 35.5,67.18 v1(35.96,67.64) ; v1(35.96,67.64) 35.5,68.11 ; v1(35.96,67.64) 36.43,67.18 ; v1(35.96,67.64) 36.43,68.11 ; 10.93,11.11 v2(12.46,12.64) ; v2(12.46,12.64) 14,11.11 ; v2(12.46,12.64) 10.93,14.18 ; v2(12.46,12.64) 14,14.18 ; v1(33.18,29.84) 33.65,30.31 ; v1(33.18,29.84) 32.72,30.31 ; v1(33.18,29.84) 33.65,29.38 ; 12.96,160.82 v1(13.42,161.28) ; v1(13.42,161.28) 13.89,160.82 ; v1(13.42,161.28) 12.96,161.75 ; v1(13.42,161.28) 13.89,161.75 ; v1(8.96,151.64) 9.43,151.18 ; v1(8.96,151.64) 9.43,152.11 ; v1(8.96,151.64) 8.5,151.18 ; v1(8.96,151.64) 8.5,152.11 ; v1(35.96,127.64) 36.43,127.18 ; v1(35.96,127.64) 35.5,128.11 ; v1(35.96,127.64) 35.5,127.18 ; v1(35.96,127.64) 36.43,128.11 ; v1(32.46,180.14) 32.93,180.61 ; v1(32.46,180.14) 32.93,179.68 ; v1(32.46,180.14) 32,180.61 ; v1(32.46,180.14) 32,179.68 ; v1(11.82,20.43) 12.29,20.9 ; v1(11.82,20.43) 11.36,20.9 ; v1(11.82,20.43) 12.29,19.97 ; v1(11.82,20.43) 11.36,19.97 ; v1(8.96,161.64) 9.43,161.18 ; v1(8.96,161.64) 8.5,162.11 ; v1(8.96,161.64) 8.5,161.18 ; v1(8.96,161.64) 9.43,162.11 ; 35.5,38.11 v1(35.96,37.64) ; v1(35.96,37.64) 36.43,38.11 ; v1(35.96,37.64) 36.43,37.18 ; v1(35.96,37.64) 35.5,37.18 ; v2(12.46,176.64) 14,175.11 ; v2(12.46,176.64) 10.93,178.18 ; v2(12.46,176.64) 10.93,175.11 ; v2(12.46,176.64) 14,178.18 ; 35.5,62.18 v1(35.96,62.64) ; v1(35.96,62.64) 36.43,63.11 ; v1(35.96,62.64) 36.43,62.18 ; v1(35.96,62.64) 35.5,63.11 ; 8.5,37.18 v1(8.96,37.64) ; v1(8.96,37.64) 9.43,37.18 ; v1(8.96,37.64) 9.43,38.11 ; v1(8.96,37.64) 8.5,38.11 ; v1(12.46,180.14) 12.93,179.68 ; v1(12.46,180.14) 12.93,180.61 ; v1(12.46,180.14) 12,180.61 ; v1(12.46,180.14) 12,179.68 ; 8.5,167.11 v1(8.96,166.64) ; v1(8.96,166.64) 8.5,166.18 ; v1(8.96,166.64) 9.43,166.18 ; v1(8.96,166.64) 9.43,167.11 ; 8.5,83.11 v1(8.96,82.64) ; v1(8.96,82.64) 8.5,82.18 ; v1(8.96,82.64) 9.43,83.11 ; v1(8.96,82.64) 9.43,82.18 ; 35.5,33.11 v1(35.96,32.64) ; v1(35.96,32.64) 36.43,33.11 ; v1(35.96,32.64) 36.43,32.18 ; v1(35.96,32.64) 35.5,32.18 ; v1(35.96,12.64) 36.43,12.18 ; v1(35.96,12.64) 36.43,13.11 ; v1(35.96,12.64) 35.5,12.18 ; v1(35.96,12.64) 35.5,13.11 ; v1(31.2,172.02) 31.67,172.49 ; v1(31.2,172.02) 31.67,171.56 ; v1(31.2,172.02) 30.74,171.56 ; v1(31.2,172.02) 30.74,172.49 ; 35.5,112.18 v1(35.96,112.64) ; v1(35.96,112.64) 35.5,113.11 ; v1(35.96,112.64) 36.43,112.18 ; v1(35.96,112.64) 36.43,113.11 ; v1(24.64,66.99) 25.11,67.46 ; v1(24.64,66.99) 24.18,67.46 ; v1(24.64,66.99) 24.18,66.53 ; v1(24.64,66.99) 25.11,66.53 ; 25.52,12.53 v1(25.98,12.99) ; v1(25.98,12.99) 25.52,13.46 ; v1(25.98,12.99) 26.45,12.53 ; v1(25.98,12.99) 26.45,13.46 ; 24.82,128.97 v1(25.28,129.43) ; v1(25.28,129.43) 24.82,129.9 ; v1(25.28,129.43) 25.75,128.97 ; v1(25.28,129.43) 25.75,129.9 ; v1(35.96,161.64) 36.43,161.18 ; v1(35.96,161.64) 35.5,162.11 ; v1(35.96,161.64) 35.5,161.18 ; v1(35.96,161.64) 36.43,162.11 ; v1(22.28,25.65) 22.75,26.12 ; v1(22.28,25.65) 21.82,25.19 ; v1(22.28,25.65) 22.75,25.19 ; v1(22.28,25.65) 21.82,26.12 ; 8.5,103.11 v1(8.96,102.64) ; v1(8.96,102.64) 9.43,102.18 ; v1(8.96,102.64) 9.43,103.11 ; v1(8.96,102.64) 8.5,102.18 ; 35.5,132.18 v1(35.96,132.64) ; v1(35.96,132.64) 36.43,133.11 ; v1(35.96,132.64) 36.43,132.18 ; v1(35.96,132.64) 35.5,133.11 ; v1(8.96,77.64) 9.43,77.18 ; v1(8.96,77.64) 9.43,78.11 ; v1(8.96,77.64) 8.5,78.11 ; v1(8.96,77.64) 8.5,77.18 ; 36.43,78.11 v1(35.96,77.64) 36.43,77.18 ; 35.5,151.18 v1(35.96,151.64) ; v1(35.96,151.64) 36.43,152.11 ; v1(35.96,151.64) 36.43,151.18 ; v1(35.96,151.64) 35.5,152.11 ; 35.5,28.11 v1(35.96,27.64) ; v1(35.96,27.64) 35.5,27.18 ; v1(35.96,27.64) 36.43,28.11 ; v1(35.96,27.64) 36.43,27.18 ; 35.5,157.11 v1(35.96,156.64) ; v1(35.96,156.64) 36.43,157.11 ; v1(35.96,156.64) 36.43,156.18 ; v1(35.96,156.64) 35.5,156.18
  BOTTOM w0.15: 22.93,17.97 v1(23.39,17.5) ; v1(23.39,17.5) 23.86,17.04 ; v1(23.39,17.5) 23.86,17.97 ; v1(23.39,17.5) 22.93,17.04 ; 30.93,11.11 v2(32.46,12.64) ; v2(32.46,12.64) 30.93,14.18 ; v2(32.46,12.64) 34,11.11 ; v2(32.46,12.64) 34,14.18 ; 17,179.68 v1(17.46,180.14) ; v1(17.46,180.14) 17,180.61 ; v1(17.46,180.14) 17.93,179.68 ; v1(17.46,180.14) 17.93,180.61 ; 35.5,42.18 v1(35.96,42.64) ; v1(35.96,42.64) 35.5,43.11 ; v1(35.96,42.64) 36.43,43.11 ; v1(35.96,42.64) 36.43,42.18 ; 35.5,27.18 v1(35.96,27.64) ; v1(35.96,27.64) 35.5,28.11 ; v1(35.96,27.64) 36.43,28.11 ; v1(35.96,27.64) 36.43,27.18 ; v1(30.78,21.3) 31.25,20.84 ; v1(30.78,21.3) 30.32,21.77 ; v1(30.78,21.3) 31.25,21.77 ; v1(30.78,21.3) 30.32,20.84 ; v1(8.96,161.64) 9.43,161.18 ; v1(8.96,161.64) 8.5,162.11 ; v1(8.96,161.64) 9.43,162.11 ; v1(8.96,161.64) 8.5,161.18 ; 12,180.61 v1(12.46,180.14) ; v1(12.46,180.14) 12.93,179.68 ; v1(12.46,180.14) 12,179.68 ; v1(12.46,180.14) 12.93,180.61 ; 8.5,113.11 v1(8.96,112.64) ; v1(8.96,112.64) 9.43,112.18 ; v1(8.96,112.64) 9.43,113.11 ; v1(8.96,112.64) 8.5,112.18 ; v1(22.88,174.7) 23.35,175.17 ; v1(22.88,174.7) 22.42,175.17 ; v1(22.88,174.7) 23.35,174.24 ; v1(22.88,174.7) 22.42,174.24 ; 35.5,12.18 v1(35.96,12.64) ; v1(35.96,12.64) 36.43,13.11 ; v1(35.96,12.64) 36.43,12.18 ; v1(35.96,12.64) 35.5,13.11 ; v1(35.96,137.64) 36.43,138.11 ; v1(35.96,137.64) 35.5,137.18 ; v1(35.96,137.64) 36.43,137.18 ; v1(35.96,137.64) 35.5,138.11 ; 12.9,122.23 v1(13.36,121.76) ; v1(13.36,121.76) 12.9,121.3 ; v1(13.36,121.76) 13.83,121.3 ; v1(13.36,121.76) 13.83,122.23 ; v1(21.73,77.48) 22.2,77.95 ; v1(21.73,77.48) 21.27,77.02 ; v1(21.73,77.48) 21.27,77.95 ; v1(21.73,77.48) 22.2,77.02 ; 8.5,22.18 v1(8.96,22.64) ; v1(8.96,22.64) 8.5,23.11 ; v1(8.96,22.64) 9.43,23.11 ; v1(8.96,22.64) 9.43,22.18 ; v1(35.96,52.64) 36.43,53.11 ; v1(35.96,52.64) 35.5,53.11 ; v1(35.96,52.64) 35.5,52.18 ; v1(35.96,52.64) 36.43,52.18 ; 11.63,36.07 v1(12.09,36.53) ; v1(12.09,36.53) 12.56,36.07 ; v1(12.09,36.53) 12.56,37 ; v1(12.09,36.53) 11.63,37 ; v1(8.96,52.64) 9.43,53.11 ; v1(8.96,52.64) 9.43,52.18 ; v1(8.96,52.64) 8.5,52.18 ; v1(8.96,52.64) 8.5,53.11 ; v1(35.96,22.64) 36.43,23.11 ; v1(35.96,22.64) 36.43,22.18 ; v1(35.96,22.64) 35.5,23.11 ; v1(35.96,22.64) 35.5,22.18 ; v1(20.42,50.65) 20.89,51.12 ; v1(20.42,50.65) 19.96,51.12 ; v1(20.42,50.65) 19.96,50.19 ; v1(20.42,50.65) 20.89,50.19 ; 8.5,167.11 v1(8.96,166.64) ; v1(8.96,166.64) 9.43,167.11 ; v1(8.96,166.64) 8.5,166.18 ; v1(8.96,166.64) 9.43,166.18 ; v1(20.74,166.26) 21.21,166.73 ; v1(20.74,166.26) 20.28,165.8 ; v1(20.74,166.26) 20.28,166.73 ; v1(20.74,166.26) 21.21,165.8 ; v1(8.96,171.64) 9.43,172.11 ; v1(8.96,171.64) 8.5,171.18 ; v1(8.96,171.64) 8.5,172.11 ; v1(8.96,171.64) 9.43,171.18 ; 11.24,29.8 v1(11.7,30.26) ; v1(11.7,30.26) 12.17,30.73 ; v1(11.7,30.26) 11.24,30.73 ; v1(11.7,30.26) 12.17,29.8 ; 11.36,20.9 v1(11.82,20.43) ; v1(11.82,20.43) 12.29,20.9 ; v1(11.82,20.43) 12.29,19.97 ; v1(11.82,20.43) 11.36,19.97 ; 35.5,33.11 v1(35.96,32.64) ; v1(35.96,32.64) 36.43,33.11 ; v1(35.96,32.64) 36.43,32.18 ; v1(35.96,32.64) 35.5,32.18 ; 30.74,171.56 v1(31.2,172.02) ; v1(31.2,172.02) 31.67,171.56 ; v1(31.2,172.02) 31.67,172.49 ; v1(31.2,172.02) 30.74,172.49 ; 8.5,117.18 v1(8.96,117.64) ; v1(8.96,117.64) 8.5,118.11 ; v1(8.96,117.64) 9.43,118.11 ; v1(8.96,117.64) 9.43,117.18 ; 28.02,21.45 v1(28.48,20.98) ; v1(28.48,20.98) 28.02,20.52 ; v1(28.48,20.98) 28.95,21.45 ; v1(28.48,20.98) 28.95,20.52 ; 35.5,172.11 v1(35.96,171.64) ; v1(35.96,171.64) 35.5,171.18 ; v1(35.96,171.64) 36.43,172.11 ; v1(35.96,171.64) 36.43,171.18 ; 8.5,58.11 v1(8.96,57.64) ; v1(8.96,57.64) 9.43,58.11 ; v1(8.96,57.64) 9.43,57.18 ; v1(8.96,57.64) 8.5,57.18 ; v1(35.96,161.64) 36.43,161.18 ; v1(35.96,161.64) 35.5,162.11 ; v1(35.96,161.64) 36.43,162.11 ; v1(35.96,161.64) 35.5,161.18 ; 22.65,21.17 v1(23.11,20.7) ; v1(23.11,20.7) 23.58,20.24 ; v1(23.11,20.7) 23.58,21.17 ; v1(23.11,20.7) 22.65,20.24 ; 24.82,128.97 v1(25.28,129.43) ; v1(25.28,129.43) 25.75,128.97 ; v1(25.28,129.43) 25.75,129.9 ; v1(25.28,129.43) 24.82,129.9 ; 35.5,83.11 v1(35.96,82.64) ; v1(35.96,82.64) 35.5,82.18 ; v1(35.96,82.64) 36.43,83.11 ; v1(35.96,82.64) 36.43,82.18 ; 24.18,67.46 v1(24.64,66.99) ; v1(24.64,66.99) 25.11,66.53 ; v1(24.64,66.99) 25.11,67.46 ; v1(24.64,66.99) 24.18,66.53 ; 35.5,67.18 v1(35.96,67.64) ; v1(35.96,67.64) 35.5,68.11 ; v1(35.96,67.64) 36.43,67.18 ; v1(35.96,67.64) 36.43,68.11 ; v1(8.96,17.64) 9.43,18.11 ; v1(8.96,17.64) 9.43,17.18 ; v1(8.96,17.64) 8.5,18.11 ; v1(8.96,17.64) 8.5,17.18 ; v1(35.96,151.64) 36.43,151.18 ; v1(35.96,151.64) 35.5,151.18 ; v1(35.96,151.64) 35.5,152.11 ; v1(35.96,151.64) 36.43,152.11 ; v1(35.96,87.64) 36.43,87.18 ; v1(35.96,87.64) 36.43,88.11 ; v1(35.96,87.64) 35.5,88.11 ; v1(35.96,87.64) 35.5,87.18 ; v1(17.93,68.37) 18.4,68.84 ; v1(17.93,68.37) 18.4,67.91 ; v1(17.93,68.37) 17.47,67.91 ; v1(17.93,68.37) 17.47,68.84 ; v1(35.96,112.64) 36.43,113.11 ; v1(35.96,112.64) 35.5,112.18 ; v1(35.96,112.64) 36.43,112.18 ; v1(35.96,112.64) 35.5,113.11 ; 31.89,17.43 v1(32.35,16.96) ; v1(32.35,16.96) 31.89,16.5 ; v1(32.35,16.96) 32.82,16.5 ; v1(32.35,16.96) 32.82,17.43 ; v1(22.28,148.93) 22.75,149.4 ; v1(22.28,148.93) 21.82,148.47 ; v1(22.28,148.93) 21.82,149.4 ; v1(22.28,148.93) 22.75,148.47 ; 23.16,61.54 v1(23.62,62) ; v1(23.62,62) 24.09,61.54 ; v1(23.62,62) 23.16,62.47 ; v1(23.62,62) 24.09,62.47 ; 35.5,177.11 v1(35.96,176.64) ; v1(35.96,176.64) 35.5,176.18 ; v1(35.96,176.64) 36.43,176.18 ; v1(35.96,176.64) 36.43,177.11 ; v1(35.96,57.64) 36.43,58.11 ; v1(35.96,57.64) 35.5,58.11 ; v1(35.96,57.64) 35.5,57.18 ; v1(35.96,57.64) 36.43,57.18 ; 32,8.68 v1(32.46,9.14) ; v1(32.46,9.14) 32,9.61 ; v1(32.46,9.14) 32.93,9.61 ; v1(32.46,9.14) 32.93,8.68 ; v1(8.96,97.64) 9.43,97.18 ; v1(8.96,97.64) 8.5,98.11 ; v1(8.96,97.64) 8.5,97.18 ; v1(8.96,97.64) 9.43,98.11 ; v1(8.96,12.64) 9.43,12.18 ; v1(8.96,12.64) 8.5,13.11 ; v1(8.96,12.64) 9.43,13.11 ; v1(8.96,12.64) 8.5,12.18 ; v1(35.96,37.64) 36.43,38.11 ; v1(35.96,37.64) 36.43,37.18 ; v1(35.96,37.64) 35.5,37.18 ; v1(35.96,37.64) 35.5,38.11 ; 8.5,63.11 v1(8.96,62.64) ; v1(8.96,62.64) 9.43,63.11 ; v1(8.96,62.64) 8.5,62.18 ; v1(8.96,62.64) 9.43,62.18 ; v1(8.96,92.64) 9.43,92.18 ; v1(8.96,92.64) 9.43,93.11 ; v1(8.96,92.64) 8.5,92.18 ; v1(8.96,92.64) 8.5,93.11 ; v1(21.8,87.77) 22.27,88.24 ; v1(21.8,87.77) 21.34,88.24 ; v1(21.8,87.77) 21.34,87.31 ; v1(21.8,87.77) 22.27,87.31 ; 35.5,93.11 v1(35.96,92.64) ; v1(35.96,92.64) 35.5,92.18 ; v1(35.96,92.64) 36.43,93.11 ; v1(35.96,92.64) 36.43,92.18 ; 25.52,12.53 v1(25.98,12.99) ; v1(25.98,12.99) 26.45,12.53 ; v1(25.98,12.99) 25.52,13.46 ; v1(25.98,12.99) 26.45,13.46 ; 35.5,133.11 v1(35.96,132.64) ; v1(35.96,132.64) 36.43,132.18 ; v1(35.96,132.64) 36.43,133.11 ; v1(35.96,132.64) 35.5,132.18 ; 8.5,151.18 v1(8.96,151.64) ; v1(8.96,151.64) 8.5,152.11 ; v1(8.96,151.64) 9.43,151.18 ; v1(8.96,151.64) 9.43,152.11 ; 8.5,43.11 v1(8.96,42.64) ; v1(8.96,42.64) 9.43,42.18 ; v1(8.96,42.64) 9.43,43.11 ; v1(8.96,42.64) 8.5,42.18 ; v1(35.96,166.64) 36.43,166.18 ; v1(35.96,166.64) 35.5,167.11 ; v1(35.96,166.64) 36.43,167.11 ; v1(35.96,166.64) 35.5,166.18 ; 8.5,146.18 v1(8.96,146.64) ; v1(8.96,146.64) 8.5,147.11 ; v1(8.96,146.64) 9.43,146.18 ; v1(8.96,146.64) 9.43,147.11 ; v1(35.96,17.64) 36.43,18.11 ; v1(35.96,17.64) 35.5,17.18 ; v1(35.96,17.64) 36.43,17.18 ; v1(35.96,17.64) 35.5,18.11 ; 35.5,156.18 v1(35.96,156.64) ; v1(35.96,156.64) 36.43,156.18 ; v1(35.96,156.64) 36.43,157.11 ; v1(35.96,156.64) 35.5,157.11 ; 8.5,83.11 v1(8.96,82.64) ; v1(8.96,82.64) 9.43,83.11 ; v1(8.96,82.64) 8.5,82.18 ; v1(8.96,82.64) 9.43,82.18 ; v2(12.46,12.64) 14,11.11 ; v2(12.46,12.64) 14,14.18 ; v2(12.46,12.64) 10.93,11.11 ; v2(12.46,12.64) 10.93,14.18 ; 24.09,50.93 v1(24.55,51.39) ; v1(24.55,51.39) 24.09,51.86 ; v1(24.55,51.39) 25.02,50.93 ; v1(24.55,51.39) 25.02,51.86 ; v1(35.96,117.64) 36.43,118.11 ; v1(35.96,117.64) 35.5,117.18 ; v1(35.96,117.64) 35.5,118.11 ; v1(35.96,117.64) 36.43,117.18 ; v1(8.96,27.64) 9.43,28.11 ; v1(8.96,27.64) 9.43,27.18 ; v1(8.96,27.64) 8.5,28.11 ; v1(8.96,27.64) 8.5,27.18 ; v1(35.96,146.64) 36.43,146.18 ; v1(35.96,146.64) 35.5,147.11 ; v1(35.96,146.64) 36.43,147.11 ; v1(35.96,146.64) 35.5,146.18 ; v1(23.55,156.86) 24.02,156.4 ; v1(23.55,156.86) 23.09,156.4 ; v1(23.55,156.86) 24.02,157.33 ; v1(23.55,156.86) 23.09,157.33 ; 12,9.61 v1(12.46,9.14) ; v1(12.46,9.14) 12.93,8.68 ; v1(12.46,9.14) 12.93,9.61 ; v1(12.46,9.14) 12,8.68 ; v1(35.96,122.64) 36.43,122.18 ; v1(35.96,122.64) 35.5,123.11 ; v1(35.96,122.64) 36.43,123.11 ; v1(35.96,122.64) 35.5,122.18 ; v1(35.96,102.64) 36.43,103.11 ; v1(35.96,102.64) 35.5,103.11 ; v1(35.96,102.64) 35.5,102.18 ; v1(35.96,102.64) 36.43,102.18 ; v1(35.96,72.64) 36.43,73.11 ; v1(35.96,72.64) 36.43,72.18 ; v1(35.96,72.64) 35.5,73.11 ; v1(35.96,72.64) 35.5,72.18 ; v1(22.46,180.14) 22.93,180.61 ; v1(22.46,180.14) 22.93,179.68 ; v1(22.46,180.14) 22,179.68 ; v1(22.46,180.14) 22,180.61 ; v1(27.01,71.72) 27.48,72.19 ; v1(27.01,71.72) 26.55,72.19 ; v1(27.01,71.72) 27.48,71.26 ; v1(27.01,71.72) 26.55,71.26 ; 10.93,178.18 v2(12.46,176.64) ; v2(12.46,176.64) 10.93,175.11 ; v2(12.46,176.64) 14,175.11 ; v2(12.46,176.64) 14,178.18 ; v1(8.96,176.64) 9.43,176.18 ; v1(8.96,176.64) 9.43,177.11 ; v1(8.96,176.64) 8.5,176.18 ; v1(8.96,176.64) 8.5,177.11 ; 35.5,107.18 v1(35.96,107.64) ; v1(35.96,107.64) 36.43,107.18 ; v1(35.96,107.64) 35.5,108.11 ; v1(35.96,107.64) 36.43,108.11 ; 8.5,67.18 v1(8.96,67.64) ; v1(8.96,67.64) 9.43,67.18 ; v1(8.96,67.64) 9.43,68.11 ; v1(8.96,67.64) 8.5,68.11 ; v1(33.18,29.84) 33.65,29.38 ; v1(33.18,29.84) 33.65,30.31 ; v1(33.18,29.84) 32.72,30.31 ; 8.5,122.18 v1(8.96,122.64) ; v1(8.96,122.64) 8.5,123.11 ; v1(8.96,122.64) 9.43,122.18 ; v1(8.96,122.64) 9.43,123.11 ; v1(33.49,57.58) 33.96,58.05 ; v1(33.49,57.58) 33.03,58.05 ; v1(33.49,57.58) 33.03,57.12 ; v1(33.49,57.58) 33.96,57.12 ; 35.5,98.11 v1(35.96,97.64) ; v1(35.96,97.64) 35.5,97.18 ; v1(35.96,97.64) 36.43,98.11 ; v1(35.96,97.64) 36.43,97.18 ; 35.5,78.11 v1(35.96,77.64) ; v1(35.96,77.64) 35.5,77.18 ; v1(35.96,77.64) 36.43,77.18 ; v1(35.96,77.64) 36.43,78.11 ; 30.93,178.18 v2(32.46,176.64) ; v2(32.46,176.64) 30.93,175.11 ; v2(32.46,176.64) 34,178.18 ; v2(32.46,176.64) 34,175.11 ; 20.31,80.7 v1(20.77,80.23) ; v1(20.77,80.23) 21.24,79.77 ; v1(20.77,80.23) 20.31,79.77 ; v1(20.77,80.23) 21.24,80.7 ; 35.5,47.18 v1(35.96,47.64) ; v1(35.96,47.64) 36.43,47.18 ; v1(35.96,47.64) 36.43,48.11 ; v1(35.96,47.64) 35.5,48.11 ; v1(8.96,72.64) 9.43,72.18 ; v1(8.96,72.64) 8.5,73.11 ; v1(8.96,72.64) 8.5,72.18 ; v1(8.96,72.64) 9.43,73.11 ; 17.08,175.17 v1(17.54,175.63) ; v1(17.54,175.63) 17.08,176.1 ; v1(17.54,175.63) 18.01,175.17 ; v1(17.54,175.63) 18.01,176.1 ; 22.1,42.24 v1(22.56,41.77) ; v1(22.56,41.77) 23.03,42.24 ; v1(22.56,41.77) 23.03,41.31 ; v1(22.56,41.77) 22.1,41.31 ; 27,8.68 v1(27.46,9.14) ; v1(27.46,9.14) 27.93,9.61 ; v1(27.46,9.14) 27,9.61 ; v1(27.46,9.14) 27.93,8.68 ; 8.5,102.18 v1(8.96,102.64) ; v1(8.96,102.64) 8.5,103.11 ; v1(8.96,102.64) 9.43,103.11 ; v1(8.96,102.64) 9.43,102.18 ; v1(21.7,133.14) 22.17,133.61 ; v1(21.7,133.14) 22.17,132.68 ; v1(21.7,133.14) 21.24,132.68 ; v1(21.7,133.14) 21.24,133.61 ; 8.5,156.18 v1(8.96,156.64) ; v1(8.96,156.64) 8.5,157.11 ; v1(8.96,156.64) 9.43,156.18 ; v1(8.96,156.64) 9.43,157.11 ; 21.91,44.99 v1(22.37,44.52) ; v1(22.37,44.52) 21.91,44.06 ; v1(22.37,44.52) 22.84,44.06 ; v1(22.37,44.52) 22.84,44.99 ; v1(8.96,32.64) 9.43,33.11 ; v1(8.96,32.64) 9.43,32.18 ; v1(8.96,32.64) 8.5,32.18 ; v1(8.96,32.64) 8.5,33.11 ; v1(35.96,127.64) 36.43,128.11 ; v1(35.96,127.64) 36.43,127.18 ; v1(35.96,127.64) 35.5,128.11 ; v1(35.96,127.64) 35.5,127.18 ; v1(8.96,37.64) 9.43,37.18 ; v1(8.96,37.64) 8.5,37.18 ; v1(8.96,37.64) 8.5,38.11 ; v1(8.96,37.64) 9.43,38.11 ; 8.5,108.11 v1(8.96,107.64) ; v1(8.96,107.64) 8.5,107.18 ; v1(8.96,107.64) 9.43,108.11 ; v1(8.96,107.64) 9.43,107.18 ; v1(22.53,136.4) 23,136.87 ; v1(22.53,136.4) 22.07,135.94 ; v1(22.53,136.4) 22.07,136.87 ; v1(22.53,136.4) 23,135.94 ; 21.82,25.19 v1(22.28,25.65) ; v1(22.28,25.65) 22.75,26.12 ; v1(22.28,25.65) 21.82,26.12 ; v1(22.28,25.65) 22.75,25.19 ; 32,179.68 v1(32.46,180.14) ; v1(32.46,180.14) 32,180.61 ; v1(32.46,180.14) 32.93,180.61 ; v1(32.46,180.14) 32.93,179.68 ; 12.96,161.75 v1(13.42,161.28) ; v1(13.42,161.28) 13.89,160.82 ; v1(13.42,161.28) 12.96,160.82 ; v1(13.42,161.28) 13.89,161.75 ; v1(26.56,170.99) 27.03,170.53 ; v1(26.56,170.99) 27.03,171.46 ; v1(26.56,170.99) 26.1,170.53 ; v1(26.56,170.99) 26.1,171.46 ; v1(27.46,180.14) 27.93,179.68 ; v1(27.46,180.14) 27,180.61 ; v1(27.46,180.14) 27,179.68 ; v1(27.46,180.14) 27.93,180.61 ; v1(35.96,62.64) 36.43,62.18 ; v1(35.96,62.64) 35.5,63.11 ; v1(35.96,62.64) 36.43,63.11 ; v1(35.96,62.64) 35.5,62.18 ; v1(35.96,141.64) 36.43,141.18 ; v1(35.96,141.64) 35.5,142.11 ; v1(35.96,141.64) 36.43,142.11 ; v1(35.96,141.64) 35.5,141.18 ; v1(8.96,87.64) 9.43,87.18 ; v1(8.96,87.64) 8.5,88.11 ; v1(8.96,87.64) 9.43,88.11 ; v1(8.96,87.64) 8.5,87.18 ; v1(8.96,77.64) 9.43,78.11 ; v1(8.96,77.64) 8.5,77.18 ; v1(8.96,77.64) 8.5,78.11 ; v1(8.96,77.64) 9.43,77.18
UNNAMED_1_CON40P_I2_A: length 14.9
  TOP w0.15: D4.2 17.48,165.41 18.14,164.75 18.74,164.75 18.79,164.8 24.56,164.8 J1.33
UNNAMED_1_CON40P_I2_A_1: length 3.7
  TOP w0.15: J1.1 27.31,119.3 26.72,119.89 D20.2
UNNAMED_1_CON40P_I2_A_2: length 10.7
  TOP w0.15: J1.6 30.71,123.13 27.71,123.13 26.62,122.04 24.18,122.04 23.33,122.88 D18.1
UNNAMED_1_CON40P_I2_A_3: length 27.7
  TOP w0.15: D5.1 10.48,165.39 12.2,163.67 23.3,163.67 27.08,159.88 27.08,157.74 28.6,156.22 30.78,156.22 J1.32
UNNAMED_1_CON40P_I2_A_4: length 21.5
  TOP w0.15: D5.2 12.98,165.39 14.34,164.03 23.45,164.03 27.68,159.79 27.68,158.02 28.3,157.4 J1.31
UNNAMED_1_CON40P_I2_A_5: length 22.6
  TOP w0.15: J1.30 30.75,153.65 27.17,153.65 26.02,154.8 15.52,154.8 13.46,156.86 13.46,157.36 12.55,158.27 D6.1
UNNAMED_1_CON40P_I2_A_6: length 7.8
  TOP w0.15: D6.2 24.55,159.97 25.46,159.06 25.46,158.56 28.47,155.56 28.73,155.56 J1.29
UNNAMED_1_CON40P_I2_A_7: length 21.1
  TOP w0.15: D4.1 14.98,165.41 16,164.39 23.59,164.39 28.08,159.9 28.08,159.71 29.07,158.72 30.74,158.72 J1.34
UNNAMED_1_CON40P_I2_A_8: length 25
  TOP w0.15: J1.22 30.79,143.53 28.17,143.53 24.92,146.79 24.92,146.87 24.7,147.09 12.39,147.09 10.48,149 D10.1
UNNAMED_1_CON40P_I2_A_9: length 19
  TOP w0.15: J1.21 27.51,144.7 25.28,146.94 25.28,147.02 24.76,147.54 14.44,147.54 12.98,149 D10.2
UNNAMED_1_CON40P_I2_A_10: length 24.3
  TOP w0.15: D8.1 10.48,152.6 11.93,151.16 24.21,151.16 26.78,148.58 30.76,148.58 J1.26
UNNAMED_1_CON40P_I2_A_11: length 11
  TOP w0.15: D15.2 20.46,129.59 22.87,132 J1.11
UNNAMED_1_CON40P_I2_A_12: length 34.9
  TOP w0.15: J1.12 30.61,130.65 24.6,130.65 20.87,126.92 20.87,124.37 20.63,124.13 8.58,124.13 8.21,124.5 8.21,129.39 8.41,129.59 D15.1
UNNAMED_1_CON40P_I2_A_13: length 18.3
  TOP w0.15: J1.25 26.09,149.78 24.36,151.52 14.07,151.52 12.98,152.6 D8.2
UNNAMED_1_CON40P_I2_A_14: length 18.5
  TOP w0.15: J1.28 30.74,151.1 25.46,151.1 24.69,151.88 15.97,151.88 15.24,152.6 D7.1
UNNAMED_1_CON40P_I2_A_15: length 12.1
  TOP w0.15: J1.27 27.99,152.32 27.01,153.3 D7.2
UNNAMED_1_CON40P_I2_A_16: length 31.5
  TOP w0.15: J1.14 30.64,133.22 23.13,133.22 21.5,134.85 8.78,134.85 8.11,135.51 8.11,140.12 8.46,140.46 D14.1
UNNAMED_1_CON40P_I2_A_17: length 14.5
  TOP w0.15: D14.2 20.51,140.46 20.87,140.1 20.87,136.51 22.84,134.54 J1.13
UNNAMED_1_CON40P_I2_A_18: length 12.7
  TOP w0.15: J1.16 30.81,135.93 24.64,135.93 21.69,138.88 D13.1
UNNAMED_1_CON40P_I2_A_19: length 6.7
  TOP w0.15: D13.2 24.19,138.88 25.99,137.08 J1.15
UNNAMED_1_CON40P_I2_A_20: length 12.9
  TOP w0.15: J1.18 30.7,138.36 27.7,138.36 25.01,141.05 22.52,141.05 21.69,141.88 D12.1
UNNAMED_1_CON40P_I2_A_21: length 6.5
  TOP w0.15: D12.2 26.18,142.58 28.22,140.54 28.5,140.54 J1.17
UNNAMED_1_CON40P_I2_A_22: length 12.7
  TOP w0.15: J1.23 27.33,147.24 24.87,149.7 D9.2
UNNAMED_1_CON40P_I2_A_23: length 19.1
  TOP w0.15: J1.24 30.85,146.13 26.85,146.13 25.03,147.95 16.29,147.95 15.24,149 D9.1
UNNAMED_1_CON40P_I2_A_24: length 6.6
  TOP w0.15: J1.19 28.41,143.17 28.03,143.17 25.62,145.58 D11.2
UNNAMED_1_CON40P_I2_A_25: length 13.1
  TOP w0.15: J1.20 30.7,140.9 28.36,140.9 25.11,144.15 22.42,144.15 21.69,144.88 D11.1
UNNAMED_1_CON40P_I2_A_26: length 4.9
  TOP w0.15: J1.9 27.41,129.46 25.83,127.88 D16.2
UNNAMED_1_CON40P_I2_A_27: length 11.2
  TOP w0.15: D16.1 23.33,126.48 23.99,125.82 24.69,125.82 24.79,125.73 26.51,125.73 29.06,128.28 30.78,128.28 J1.10
UNNAMED_1_CON40P_I2_A_28: length 17
  TOP w0.15: D17.1 19.29,122.9 20.44,121.75 22,121.75 22.51,122.26 22.51,124.9 22.68,125.07 24.43,125.07 24.49,125.01 26.81,125.01 27.17,125.37 30.41,125.37 J1.8
UNNAMED_1_CON40P_I2_A_29: length 10.7
  TOP w0.15: D17.2 21.49,124.03 21.5,124.04 21.5,125.02 21.91,125.43 24.57,125.43 24.64,125.37 26.66,125.37 28.21,126.92 J1.7
UNNAMED_1_CON40P_I2_A_30: length 3.9
  TOP w0.15: D18.2 28.62,123.58 J1.5
UNNAMED_1_CON40P_I2_A_31: length 10.2
  TOP w0.15: J1.2 30.71,118.05 24.63,118.05 23.49,119.19 D20.1
UNNAMED_1_CON40P_I2_A_32: length 9.5
  TOP w0.15: J1.3 26.93,121.84 26.77,121.68 22.44,121.68 22.15,121.39 22.12,121.39 21.49,120.76 D19.2
UNNAMED_1_CON40P_I2_A_33: length 16.4
  TOP w0.15: J1.4 30.67,120.55 27.62,120.55 26.86,121.32 22.9,121.32 22.65,121.07 22.65,119.08 22.12,118.55 20.24,118.55 19.29,119.5 D19.1
UNNAMED_1_CON40P_I2_A_34: length 25.9
  TOP w0.15: J1.36 30.89,161.41 28.59,161.41 22.47,167.54 12.34,167.54 10.48,169.39 D3.1
UNNAMED_1_CON40P_I2_A_35: length 20.5
  TOP w0.15: D2.1 14.98,169.39 15.94,168.43 23.33,168.43 27.97,163.79 30.73,163.79 J1.38
UNNAMED_1_CON40P_I2_A_36: length 14
  TOP w0.15: D2.2 22.32,170.09 27.39,165.02 J1.37
UNNAMED_1_CON40P_I2_A_37: length 20
  TOP w0.15: D3.2 12.98,169.39 14.32,168.05 22.6,168.05 28.17,162.48 J1.35
UNNAMED_1_CON40P_I2_A_38: length 14.2
  TOP w0.15: J1.39 26.46,167.56 20.97,173.05 18.6,173.05 18.56,173.09 D1.2
UNNAMED_1_CON40P_I2_A_39: length 19.5
  TOP w0.15: D1.1 15.83,173.09 17.35,171.57 21.89,171.57 27.12,166.34 30.74,166.34 J1.40
UNNAMED_1_CON40P_I21_A: length 34.4
  TOP w0.15: J2.11 13.06,82.21 14.46,82.21 22.92,73.75 22.92,73.75 23.24,73.42 35.51,73.42 35.87,73.79 35.87,76.87 35.35,77.39 35.35,78.66 35.17,78.84 D35.2
UNNAMED_1_CON40P_I21_A_1: length 13.6
  TOP w0.15: D23.2 21.79,109.37 20.99,108.57 18.46,108.57 16.71,110.32 16.71,111.56 15.77,112.5 13.25,112.5 J2.35
UNNAMED_1_CON40P_I21_A_2: length 6.6
  TOP w0.15: J2.36 16.03,113.68 18.22,111.49 18.57,111.49 19.29,110.77 D23.1
UNNAMED_1_CON40P_I21_A_3: length 11.3
  TOP w0.15: J2.12 18.97,78.84 D35.1
UNNAMED_1_CON40P_I21_A_4: length 12.1
  TOP w0.15: D27.2 21.79,101.12 20.95,100.28 18.28,100.28 16.4,102.16 13.43,102.16 J2.27
UNNAMED_1_CON40P_I21_A_5: length 5.8
  TOP w0.15: J2.28 18.21,103.52 18.66,103.07 18.74,103.07 19.29,102.52 D27.1
UNNAMED_1_CON40P_I21_A_6: length 33.3
  TOP w0.15: D33.2 35.27,89.52 35.36,89.61 35.92,89.61 36.69,88.84 36.69,85.09 35.73,84.13 23.09,84.13 20.2,87.02 13.33,87.02 J2.15
UNNAMED_1_CON40P_I21_A_7: length 10.1
  TOP w0.15: J2.16 19.66,88.28 20.9,89.52 D33.1
UNNAMED_1_CON40P_I21_A_8: length 44.8
  TOP w0.15: D24.2 35.27,100.1 35.3,100.07 35.83,100.07 36.91,98.99 36.91,96.01 35.7,94.8 23.11,94.8 22.62,95.3 22.62,100.11 22.52,100.21 22.52,104.86 21.94,105.44 21.94,105.98 21.42,106.5 21.42,107.69 21.29,107.83 18.12,107.83 15.72,110.22 15.09,110.22 15.02,110.16 13.06,110.16 J2.33
UNNAMED_1_CON40P_I21_A_9: length 18.1
  TOP w0.15: D24.1 24.22,100.08 23.16,100.08 22.88,100.36 22.88,105.01 22.3,105.59 22.3,106.13 21.79,106.64 21.79,107.83 21.44,108.19 18.34,108.19 16.35,110.17 16.35,110.39 15.6,111.14 J2.34
UNNAMED_1_CON40P_I21_A_10: length 5.2
  TOP w0.15: J2.22 17.19,95.9 18.47,94.62 D30.1
UNNAMED_1_CON40P_I21_A_11: length 43.4
  TOP w0.15: D21.2 35.27,111.59 35.29,111.61 35.46,111.61 36.93,110.14 36.93,106.13 36.13,105.33 23.06,105.33 22.66,105.74 22.66,112.67 22.65,112.67 22.65,114.8 19.98,117.47 13.36,117.47 J2.39
UNNAMED_1_CON40P_I21_A_12: length 11
  TOP w0.15: D30.2 21.49,94.47 20.53,93.51 18.74,93.51 18.47,93.78 18.47,93.9 17.6,94.76 13.21,94.76 J2.21
UNNAMED_1_CON40P_I21_A_13: length 14.1
  TOP w0.15: D21.1 24.24,111.94 23.01,113.17 23.01,115.36 20.39,117.98 15.39,117.98 J2.40
UNNAMED_1_CON40P_I21_A_14: length 4.8
  TOP w0.15: D32.1 18.47,90.62 18.27,90.82 J2.18
UNNAMED_1_CON40P_I21_A_15: length 10.3
  TOP w0.15: J2.17 13.28,89.61 20.48,89.61 D32.2
UNNAMED_1_CON40P_I21_A_16: length 14.9
  TOP w0.15: J2.1 12.07,60.96 12.75,60.28 15.04,60.28 16.01,61.25 D40.2
UNNAMED_1_CON40P_I21_A_17: length 9
  TOP w0.15: D40.1 13.51,68.64 13.57,68.7 13.57,69.46 J2.2
UNNAMED_1_CON40P_I21_A_18: length 11.8
  TOP w0.15: D22.2 21.49,112.92 20.42,111.85 18.37,111.85 15.27,114.95 13.34,114.95 J2.37
UNNAMED_1_CON40P_I21_A_19: length 6.1
  TOP w0.15: D22.1 19.29,113.22 16.29,116.22 J2.38
UNNAMED_1_CON40P_I21_A_20: length 15.8
  TOP w0.15: J2.3 13.43,71.68 15.35,71.68 15.78,71.25 15.78,68.99 15.06,68.27 15.06,64.37 15.59,63.84 17.51,63.84 18.47,64.8 D39.2
UNNAMED_1_CON40P_I21_A_21: length 12.6
  TOP w0.15: J2.8 20.97,71.76 20.97,70.57 21.77,69.78 21.94,69.78 22.62,69.1 D37.1
UNNAMED_1_CON40P_I21_A_22: length 8.9
  TOP w0.15: J2.4 16.4,71.25 16.4,66.06 16.27,65.93 D39.1
UNNAMED_1_CON40P_I21_A_23: length 19.4
  TOP w0.15: D37.2 24.82,68.8 23.52,67.5 21.45,67.5 20.78,68.17 20.78,70.19 16.11,74.86 16.11,75.53 14.73,76.92 13.27,76.92 J2.7
UNNAMED_1_CON40P_I21_A_24: length 9.9
  TOP w0.15: D25.2 20.03,106.44 18.11,106.44 17.13,107.42 13.25,107.42 J2.31
UNNAMED_1_CON40P_I21_A_25: length 5.3
  TOP w0.15: D25.1 18.24,107.2 17.61,107.83 15.38,107.83 J2.32
UNNAMED_1_CON40P_I21_A_26: length 13
  TOP w0.15: D38.1 20.32,68.63 20.34,68.65 20.34,69.85 J2.6
UNNAMED_1_CON40P_I21_A_27: length 12
  TOP w0.15: D28.2 21.37,98.82 19.94,97.4 18.67,97.4 16.23,99.83 13.22,99.83 J2.25
UNNAMED_1_CON40P_I21_A_28: length 20.5
  TOP w0.15: D38.2 22.82,64.25 22.16,63.59 21.46,63.59 21.25,63.38 19.71,63.38 19.3,63.79 19.3,69.75 14.87,74.18 13.28,74.18 13.13,74.33 13.13,74.52 J2.5
UNNAMED_1_CON40P_I21_A_29: length 5.6
  TOP w0.15: D28.1 18.67,98.82 16.51,100.98 J2.26
UNNAMED_1_CON40P_I21_A_30: length 12.9
  TOP w0.15: D36.1 22.22,73.05 J2.10
UNNAMED_1_CON40P_I21_A_31: length 5.1
  TOP w0.15: J2.20 18.38,93.36 18.59,93.15 18.96,93.15 19.29,92.82 D31.1
UNNAMED_1_CON40P_I21_A_32: length 5.8
  TOP w0.15: D34.1 19.29,83.35 16.9,85.74 J2.14
UNNAMED_1_CON40P_I21_A_33: length 12.4
  TOP w0.15: D34.2 21.49,82.02 21.34,81.87 17.08,81.87 16.93,82.02 16.93,82.27 14.6,84.61 13.2,84.61 J2.13
UNNAMED_1_CON40P_I21_A_34: length 5.4
  TOP w0.15: J2.24 16.95,98.44 18.77,96.62 D29.1
UNNAMED_1_CON40P_I21_A_35: length 19
  TOP w0.15: D36.2 24.82,70.75 24.21,70.14 21.92,70.14 21.4,70.65 21.4,73.18 15.02,79.56 13.17,79.56 J2.9
UNNAMED_1_CON40P_I21_A_36: length 10.9
  TOP w0.15: D31.2 21.89,92.42 21.24,91.77 18.09,91.77 17.65,92.21 13.22,92.21 J2.19
UNNAMED_1_CON40P_I21_A_37: length 11.4
  TOP w0.15: J2.23 13.16,97.35 17.13,97.35 18.76,95.72 21.19,95.72 21.89,96.42 D29.2
UNNAMED_1_CON40P_I21_A_38: length 5.2
  TOP w0.15: D26.1 18.77,104.82 17.53,106.06 J2.30
UNNAMED_1_CON40P_I21_A_39: length 10.6
  TOP w0.15: J2.29 13.35,104.78 17.46,104.78 18.81,103.43 19.72,103.43 20.91,104.62 D26.2
UNNAMED_1_CON40P_I55_A: length 13.3
  TOP w0.15: D46.2 22.54,52.15 28.11,57.72 28.11,57.87 J3.29
UNNAMED_1_CON40P_I55_A_1: length 33.4
  TOP w0.15: J3.30 30.9,58.12 29.1,58.12 26.07,55.1 26.07,49.72 19.33,42.98 14.67,42.98 11.95,45.7 11.95,46.2 11.04,47.11 D46.1
UNNAMED_1_CON40P_I55_A_2: length 22.8
  TOP w0.15: J3.40 30.89,70.81 29.33,70.81 28.3,69.78 28.3,68.19 27.8,67.69 27.8,67.09 25.25,64.54 25.25,61.92 23.28,59.95 19.57,59.95 18.27,61.25 D41.1
UNNAMED_1_CON40P_I55_A_3: length 14.3
  TOP w0.15: J3.39 27.94,70.4 27.94,68.46 24.96,65.48 24.96,64.91 22,61.95 D41.2
UNNAMED_1_CON40P_I55_A_4: length 26.7
  TOP w0.15: J3.6 30.95,27.69 28.28,27.69 26.55,25.96 26.55,20.72 24.96,19.13 15.46,19.13 13.77,20.82 D58.1
UNNAMED_1_CON40P_I55_A_5: length 21.5
  TOP w0.15: D58.2 16.27,20.82 17.6,19.49 24.69,19.49 25.92,20.72 25.92,26.19 28.52,28.78 J3.5
UNNAMED_1_CON40P_I55_A_6: length 22.4
  TOP w0.15: J3.12 30.49,34.85 29.1,34.85 23.42,29.17 23.42,24.95 22.46,23.99 19.1,23.99 18.27,24.82 D55.1
UNNAMED_1_CON40P_I55_A_7: length 14.8
  TOP w0.15: J3.11 22.94,29.84 22.94,27.91 21.85,26.82 21.37,26.82 20.77,26.22 D55.2
UNNAMED_1_CON40P_I55_A_8: length 26.3
  TOP w0.15: D56.1 13.77,24.82 15.52,23.07 22.94,23.07 24.34,24.47 24.34,28.07 28.91,32.64 30.82,32.64 J3.10
UNNAMED_1_CON40P_I55_A_9: length 23.1
  TOP w0.15: J3.8 30.96,30.24 28.86,30.24 25.49,26.87 25.49,21 24.34,19.85 19.24,19.85 18.27,20.82 D57.1
UNNAMED_1_CON40P_I55_A_10: length 20.7
  TOP w0.15: J3.9 23.81,28.17 23.81,24.71 22.7,23.6 17.49,23.6 16.27,24.82 D56.2
UNNAMED_1_CON40P_I55_A_11: length 15.9
  TOP w0.15: D57.2 21.5,21.52 21.51,21.53 24.05,21.53 24.91,22.39 24.91,27.72 28.52,31.32 J3.7
UNNAMED_1_CON40P_I55_A_12: length 26.2
  TOP w0.15: J3.14 30.49,37.39 29.1,37.39 28.52,36.81 28.52,36.07 22.58,30.14 22.58,28.06 21.7,27.18 15.41,27.18 13.77,28.82 D54.1
UNNAMED_1_CON40P_I55_A_13: length 21.4
  TOP w0.15: D54.2 16.27,28.82 17.55,27.54 21.55,27.54 22.17,28.16 22.17,30.24 28.16,36.22 28.16,36.96 28.95,37.75 29.29,37.75 29.5,37.96 J3.13
UNNAMED_1_CON40P_I55_A_14: length 23.3
  TOP w0.15: D53.1 18.27,28.82 19.19,27.9 21.4,27.9 21.81,28.31 21.81,30.38 23.2,31.77 23.2,32.97 28.44,38.21 28.44,39.72 29.05,40.33 30.89,40.33 J3.16
